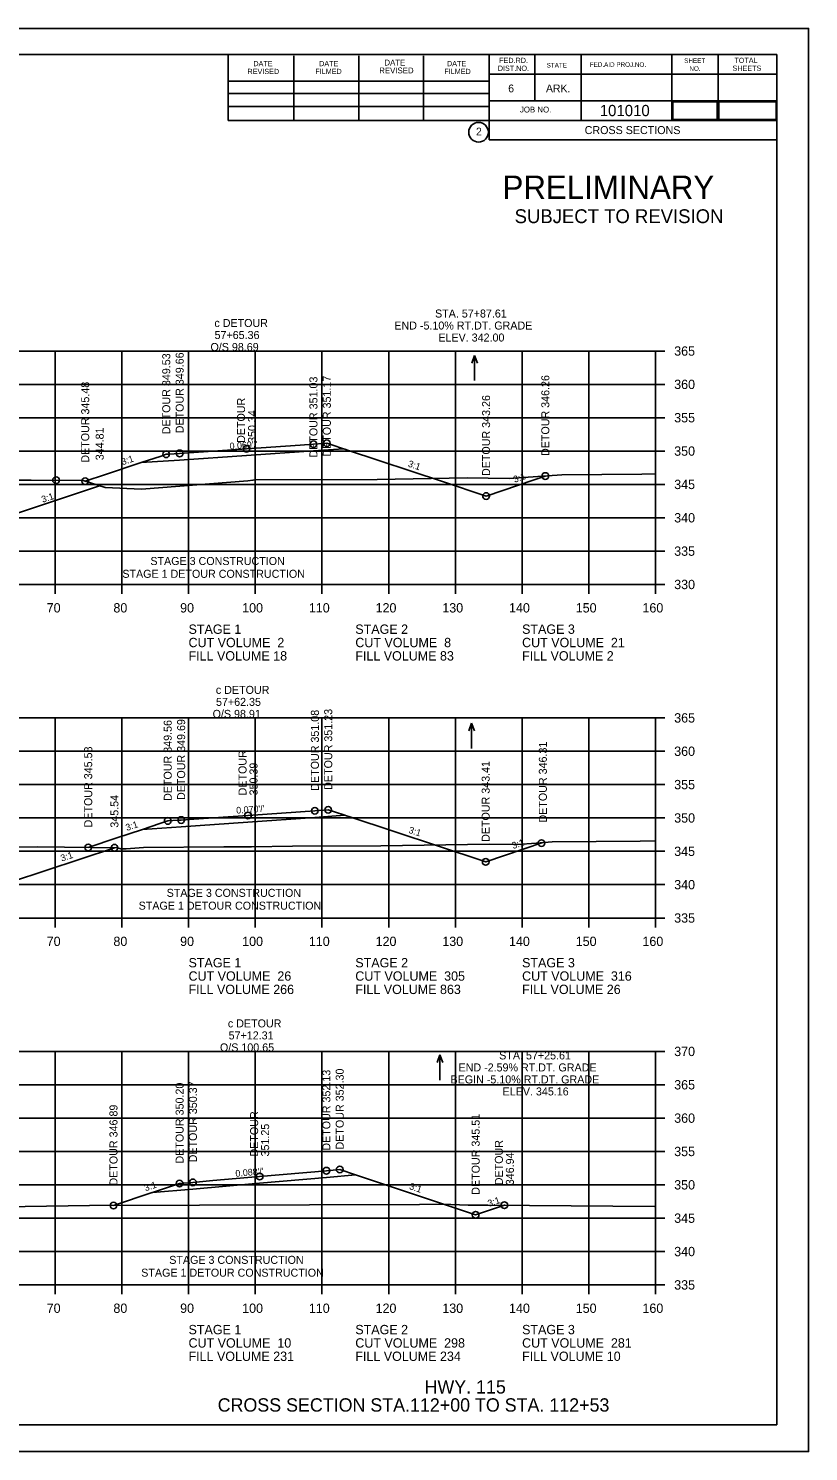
# Model space of a CAD drawing. Extents: x 1630712 to 1632516, y 782146 to 785403.
# Drawn here: x 1632399 to 1632515.9, y 784550 to 784763.3 of the extents above; entities that cross this region are included whole.
import ezdxf

# ---------------------------------------------------------------- set-up
doc = ezdxf.new("R2010")
doc.units = 0
for name, color, linetype in [('Default', 7, 'Continuous'), ('Notes', 7, 'Continuous'), ('Page Number', 7, 'Continuous'), ('R_Axis', 7, 'Continuous'), ('R_Axis Annot', 7, 'Continuous'), ('R_Border', 7, 'Continuous'), ('R_Border Notes', 7, 'Continuous'), ('R_Border Prem', 7, 'Continuous'), ('R_Detour Subgrade', 7, 'Continuous'), ('R_Detour Surface', 7, 'Continuous'), ('R_Draft', 7, 'Continuous'), ('R_Exist Surface', 7, 'Continuous'), ('R_Fin Surface', 7, 'Continuous'), ('R_Grid', 7, 'Continuous'), ('R_No Plot', 7, 'Continuous'), ('R_Water Annot', 7, 'Continuous'), ('R_Xsect Elev', 7, 'Continuous'), ('R_Xsect Elev Detour', 7, 'Continuous'), ('R_Xsect Slope', 7, 'Continuous'), ('Total_Pages', 7, 'Continuous')]:
    doc.layers.add(name, color=color, linetype=linetype)

msp = doc.modelspace()

# ---------------------------------------------------------------- linework, layer by layer
at = {"layer": 'Default'}
msp.add_line((1632396.41, 784635.37), (1632411.85, 784640.51), dxfattribs=at)
at = {"layer": 'Page Number'}
msp.add_lwpolyline([(1632495.54, 784749.7), (1632502.21, 784749.7), (1632502.21, 784752.34), (1632495.54, 784752.34)], close=True, dxfattribs=at)
at = {"layer": 'R_Axis'}
for p, q in [((1632492.96, 784679.97), (1632492.96, 784714.97)), ((1632494.36, 784714.97), (1632492.96, 784714.97)), ((1632494.36, 784709.97), (1632492.96, 784709.97)), ((1632494.36, 784704.97), (1632492.96, 784704.97)), ((1632494.36, 784699.97), (1632492.96, 784699.97)), ((1632494.36, 784694.97), (1632492.96, 784694.97)), ((1632494.36, 784689.97), (1632492.96, 784689.97)), ((1632494.36, 784684.97), (1632492.96, 784684.97)), ((1632212.96, 784679.97), (1632492.96, 784679.97)), ((1632402.96, 784678.57), (1632402.96, 784679.97)), ((1632412.96, 784678.57), (1632412.96, 784679.97)), ((1632422.96, 784678.57), (1632422.96, 784679.97)), ((1632432.96, 784678.57), (1632432.96, 784679.97)), ((1632442.96, 784678.57), (1632442.96, 784679.97)), ((1632452.96, 784678.57), (1632452.96, 784679.97)), ((1632462.96, 784678.57), (1632462.96, 784679.97)), ((1632472.96, 784678.57), (1632472.96, 784679.97)), ((1632482.96, 784678.57), (1632482.96, 784679.97)), ((1632492.96, 784678.57), (1632492.96, 784679.97)), ((1632494.36, 784679.97), (1632492.96, 784679.97)), ((1632492.96, 784629.97), (1632492.96, 784659.97)), ((1632494.36, 784659.97), (1632492.96, 784659.97)), ((1632494.36, 784654.97), (1632492.96, 784654.97)), ((1632494.36, 784649.97), (1632492.96, 784649.97)), ((1632494.36, 784644.97), (1632492.96, 784644.97)), ((1632494.36, 784639.97), (1632492.96, 784639.97)), ((1632494.36, 784634.97), (1632492.96, 784634.97)), ((1632212.96, 784629.97), (1632492.96, 784629.97)), ((1632402.96, 784628.57), (1632402.96, 784629.97)), ((1632412.96, 784628.57), (1632412.96, 784629.97)), ((1632422.96, 784628.57), (1632422.96, 784629.97)), ((1632432.96, 784628.57), (1632432.96, 784629.97)), ((1632442.96, 784628.57), (1632442.96, 784629.97)), ((1632452.96, 784628.57), (1632452.96, 784629.97)), ((1632462.96, 784628.57), (1632462.96, 784629.97)), ((1632472.96, 784628.57), (1632472.96, 784629.97)), ((1632482.96, 784628.57), (1632482.96, 784629.97)), ((1632492.96, 784628.57), (1632492.96, 784629.97)), ((1632494.36, 784629.97), (1632492.96, 784629.97)), ((1632492.96, 784574.97), (1632492.96, 784609.97)), ((1632494.36, 784609.97), (1632492.96, 784609.97)), ((1632494.36, 784604.97), (1632492.96, 784604.97)), ((1632494.36, 784599.97), (1632492.96, 784599.97)), ((1632494.36, 784594.97), (1632492.96, 784594.97)), ((1632494.36, 784589.97), (1632492.96, 784589.97)), ((1632494.36, 784584.97), (1632492.96, 784584.97)), ((1632494.36, 784579.97), (1632492.96, 784579.97)), ((1632212.96, 784574.97), (1632492.96, 784574.97)), ((1632402.96, 784573.57), (1632402.96, 784574.97)), ((1632412.96, 784573.57), (1632412.96, 784574.97)), ((1632422.96, 784573.57), (1632422.96, 784574.97)), ((1632432.96, 784573.57), (1632432.96, 784574.97)), ((1632442.96, 784573.57), (1632442.96, 784574.97)), ((1632452.96, 784573.57), (1632452.96, 784574.97)), ((1632462.96, 784573.57), (1632462.96, 784574.97)), ((1632472.96, 784573.57), (1632472.96, 784574.97)), ((1632482.96, 784573.57), (1632482.96, 784574.97)), ((1632492.96, 784573.57), (1632492.96, 784574.97)), ((1632494.36, 784574.97), (1632492.96, 784574.97))]:
    msp.add_line(p, q, dxfattribs=at)
at = {"layer": 'R_Border'}
for p, q in [((1632194.96, 784759.43), (1632511.14, 784759.43)), ((1632428.88, 784749.55), (1632428.88, 784759.43)), ((1632438.74, 784749.55), (1632438.74, 784759.23)), ((1632448.5, 784749.55), (1632448.5, 784759.23)), ((1632458.18, 784749.55), (1632458.18, 784759.23)), ((1632468.04, 784759.43), (1632468.04, 784746.63)), ((1632474.88, 784759.43), (1632474.88, 784752.49)), ((1632481.82, 784759.43), (1632481.82, 784749.55)), ((1632495.4, 784759.43), (1632495.4, 784749.55)), ((1632502.34, 784759.43), (1632502.34, 784749.55)), ((1632511.14, 784553.97), (1632511.14, 784759.43)), ((1632511.14, 784756.49), (1632468.04, 784756.49)), ((1632511.14, 784756.51), (1632511.14, 784756.51)), ((1632428.88, 784755.41), (1632468.04, 784755.41)), ((1632428.88, 784753.55), (1632468.04, 784753.55)), ((1632511.14, 784752.49), (1632468.04, 784752.49)), ((1632471, 784752.49), (1632511.14, 784752.49)), ((1632428.88, 784749.55), (1632428.88, 784751.61)), ((1632428.88, 784751.61), (1632468.04, 784751.61)), ((1632511.14, 784749.55), (1632428.88, 784749.55)), ((1632468.04, 784746.63), (1632511.14, 784746.63)), ((1632511.14, 784553.97), (1632194.96, 784553.97))]:
    msp.add_line(p, q, dxfattribs=at)
msp.add_circle((1632466.43, 784747.77), 1.47, dxfattribs=at)
at = {"layer": 'R_Detour Subgrade'}
for points in [[(1632415.85, 784698.24), (1632421.63, 784698.63), (1632431.66, 784699.31), (1632441.68, 784700), (1632446.19, 784700.31)], [(1632416.05, 784643.26), (1632421.85, 784643.66), (1632431.87, 784644.35), (1632441.9, 784645.05), (1632446.39, 784645.37)], [(1632417.54, 784588.8), (1632423.62, 784589.34), (1632433.62, 784590.22), (1632443.62, 784591.09), (1632447.99, 784591.48)]]:
    msp.add_lwpolyline(points, dxfattribs=at)
at = {"layer": 'R_Detour Surface'}
for points in [[(1632407.47, 784695.45), (1632410.52, 784696.46), (1632415.85, 784698.24), (1632418.84, 784699.23), (1632419.62, 784699.49), (1632420, 784699.52), (1632421.63, 784699.63), (1632431.64, 784700.31), (1632431.65, 784700.31), (1632431.66, 784700.31), (1632439.7, 784700.86), (1632441.68, 784701), (1632443.13, 784701.1), (1632443.69, 784701.14), (1632444.46, 784700.88), (1632446.19, 784700.31), (1632446.4, 784700.24), (1632446.79, 784700.11), (1632461.05, 784695.39), (1632467.56, 784693.23), (1632474.79, 784695.68), (1632476.44, 784696.23)], [(1632407.92, 784640.55), (1632412.23, 784641.99), (1632416.05, 784643.26), (1632418.66, 784644.13), (1632419.84, 784644.52), (1632421.35, 784644.63), (1632421.85, 784644.66), (1632423.74, 784644.79), (1632431.87, 784645.35), (1632431.88, 784645.36), (1632431.89, 784645.36), (1632441.9, 784646.05), (1632442.52, 784646.1), (1632443.9, 784646.19), (1632444.84, 784645.88), (1632446.39, 784645.37), (1632446.65, 784645.28), (1632446.99, 784645.17), (1632467.23, 784638.47), (1632467.5, 784638.38), (1632467.5, 784638.38), (1632476.07, 784641.28)], [(1632411.71, 784586.86), (1632417.53, 784588.8), (1632417.54, 784588.8), (1632417.54, 784588.81), (1632421.62, 784590.16), (1632421.62, 784590.16), (1632423.62, 784590.34), (1632423.62, 784590.34), (1632426.59, 784590.6), (1632433.62, 784591.22), (1632443.62, 784592.09), (1632445.62, 784592.27), (1632447.99, 784591.48), (1632447.99, 784591.48), (1632448.59, 784591.28), (1632448.59, 784591.28), (1632466, 784585.48), (1632466, 784585.48), (1632466, 784585.48), (1632470.3, 784586.91), (1632470.3, 784586.91), (1632470.3, 784586.91), (1632470.36, 784586.92), (1632470.36, 784586.92)]]:
    msp.add_lwpolyline(points, dxfattribs=at)
at = {"layer": 'R_Exist Surface'}
for points in [[(1632394.95, 784695.59), (1632399.38, 784695.62), (1632407.15, 784695.55), (1632410.48, 784694.51), (1632415.89, 784694.26), (1632431.85, 784695.51), (1632432.6, 784695.6), (1632432.85, 784695.65), (1632451.24, 784695.72), (1632464.73, 784695.94), (1632471.02, 784695.86), (1632475.3, 784696.16), (1632478.91, 784696.4), (1632490.89, 784696.53), (1632492.96, 784696.55)], [(1632393.57, 784640.58), (1632400.37, 784640.63), (1632412.31, 784640.51), (1632412.8, 784640.36), (1632413.59, 784640.32), (1632416.19, 784640.53), (1632428.24, 784640.65), (1632432.38, 784640.65), (1632438.53, 784640.74), (1632451.79, 784640.8), (1632468.02, 784641.06), (1632472.21, 784641.01), (1632475.06, 784641.21), (1632477.46, 784641.37), (1632490.67, 784641.51), (1632492.96, 784641.53)], [(1632385.52, 784586.5), (1632408.13, 784586.85), (1632457.56, 784587), (1632460.98, 784587.06), (1632464.86, 784586.91), (1632467.82, 784586.93), (1632492.79, 784586.74), (1632492.96, 784586.74)]]:
    msp.add_lwpolyline(points, dxfattribs=at)
at = {"layer": 'R_Fin Surface'}
for points in [[(1632396.41, 784690.37), (1632399.41, 784691.37), (1632409.63, 784694.78)], [(1632268.96, 784635.44), (1632269.96, 784635.11), (1632296.96, 784644.11), (1632310.78, 784646.18), (1632314.96, 784647.22), (1632320.96, 784647.46), (1632332.96, 784647.7), (1632344.96, 784647.46), (1632350.96, 784647.22), (1632355.15, 784646.18), (1632368.96, 784644.52), (1632396.41, 784635.37), (1632411.85, 784640.51)]]:
    msp.add_lwpolyline(points, dxfattribs=at)
at = {"layer": 'R_Grid'}
for p, q in [((1632212.96, 784714.97), (1632492.96, 784714.97)), ((1632402.96, 784679.97), (1632402.96, 784714.97)), ((1632412.96, 784679.97), (1632412.96, 784714.97)), ((1632422.96, 784679.97), (1632422.96, 784714.97)), ((1632432.96, 784679.97), (1632432.96, 784714.97)), ((1632442.96, 784679.97), (1632442.96, 784714.97)), ((1632452.96, 784679.97), (1632452.96, 784714.97)), ((1632462.96, 784679.97), (1632462.96, 784714.97)), ((1632472.96, 784679.97), (1632472.96, 784714.97)), ((1632482.96, 784679.97), (1632482.96, 784714.97)), ((1632492.96, 784679.97), (1632492.96, 784714.97)), ((1632212.96, 784709.97), (1632492.96, 784709.97)), ((1632212.96, 784704.97), (1632492.96, 784704.97)), ((1632212.96, 784699.97), (1632492.96, 784699.97)), ((1632212.96, 784694.97), (1632492.96, 784694.97)), ((1632212.96, 784689.97), (1632492.96, 784689.97)), ((1632212.96, 784684.97), (1632492.96, 784684.97)), ((1632212.96, 784679.97), (1632492.96, 784679.97)), ((1632212.96, 784659.97), (1632492.96, 784659.97)), ((1632402.96, 784629.97), (1632402.96, 784659.97)), ((1632412.96, 784629.97), (1632412.96, 784659.97)), ((1632422.96, 784629.97), (1632422.96, 784659.97)), ((1632432.96, 784629.97), (1632432.96, 784659.97)), ((1632442.96, 784629.97), (1632442.96, 784659.97)), ((1632452.96, 784629.97), (1632452.96, 784659.97)), ((1632462.96, 784629.97), (1632462.96, 784659.97)), ((1632472.96, 784629.97), (1632472.96, 784659.97)), ((1632482.96, 784629.97), (1632482.96, 784659.97)), ((1632492.96, 784629.97), (1632492.96, 784659.97)), ((1632212.96, 784654.97), (1632492.96, 784654.97)), ((1632212.96, 784649.97), (1632492.96, 784649.97)), ((1632212.96, 784644.97), (1632492.96, 784644.97)), ((1632212.96, 784639.97), (1632492.96, 784639.97)), ((1632212.96, 784634.97), (1632492.96, 784634.97)), ((1632212.96, 784629.97), (1632492.96, 784629.97)), ((1632212.96, 784609.97), (1632492.96, 784609.97)), ((1632402.96, 784574.97), (1632402.96, 784609.97)), ((1632412.96, 784574.97), (1632412.96, 784609.97)), ((1632422.96, 784574.97), (1632422.96, 784609.97)), ((1632432.96, 784574.97), (1632432.96, 784609.97)), ((1632442.96, 784574.97), (1632442.96, 784609.97)), ((1632452.96, 784574.97), (1632452.96, 784609.97)), ((1632462.96, 784574.97), (1632462.96, 784609.97)), ((1632472.96, 784574.97), (1632472.96, 784609.97)), ((1632482.96, 784574.97), (1632482.96, 784609.97)), ((1632492.96, 784574.97), (1632492.96, 784609.97)), ((1632212.96, 784604.97), (1632492.96, 784604.97)), ((1632212.96, 784599.97), (1632492.96, 784599.97)), ((1632212.96, 784594.97), (1632492.96, 784594.97)), ((1632212.96, 784589.97), (1632492.96, 784589.97)), ((1632212.96, 784584.97), (1632492.96, 784584.97)), ((1632212.96, 784579.97), (1632492.96, 784579.97)), ((1632212.96, 784574.97), (1632492.96, 784574.97))]:
    msp.add_line(p, q, dxfattribs=at)
at = {"layer": 'R_No Plot'}
for p, q in [((1632182.56, 784763.32), (1632515.9, 784763.32)), ((1632182.56, 784549.99), (1632515.9, 784549.99))]:
    msp.add_line(p, q, dxfattribs=at)
msp.add_lwpolyline([(1632182.56, 784763.32), (1632515.9, 784763.32), (1632515.9, 784549.99), (1632182.56, 784549.99)], close=True, dxfattribs=at)
for centre in [(1632431.66, 784700.31), (1632441.68, 784701), (1632443.69, 784701.14), (1632419.62, 784699.49), (1632421.63, 784699.63), (1632476.44, 784696.23), (1632403.1, 784695.59), (1632407.47, 784695.45), (1632467.56, 784693.23), (1632421.85, 784644.66), (1632431.87, 784645.35), (1632441.9, 784646.05), (1632443.9, 784646.19), (1632419.84, 784644.52), (1632407.92, 784640.55), (1632411.85, 784640.51), (1632475.85, 784641.2), (1632467.5, 784638.38), (1632433.62, 784591.22), (1632443.62, 784592.09), (1632445.62, 784592.27), (1632421.62, 784590.16), (1632423.62, 784590.34), (1632411.71, 784586.86), (1632466, 784585.48), (1632470.3, 784586.91)]:
    msp.add_circle(centre, 0.5, dxfattribs=at)
at = {"layer": 'R_Water Annot'}
for p, q in [((1632465.85, 784714.32), (1632465.43, 784713.16)), ((1632465.85, 784710.55), (1632465.85, 784714.32)), ((1632465.85, 784714.32), (1632466.27, 784713.16)), ((1632465.4, 784659.17), (1632464.98, 784658.01)), ((1632465.4, 784655.4), (1632465.4, 784659.17)), ((1632465.4, 784659.17), (1632465.82, 784658.01)), ((1632460.65, 784609.45), (1632460.23, 784608.3)), ((1632460.65, 784605.68), (1632460.65, 784609.45)), ((1632460.65, 784609.45), (1632461.07, 784608.3))]:
    msp.add_line(p, q, dxfattribs=at)
at = {"layer": 'Total_Pages'}
msp.add_lwpolyline([(1632502.44, 784749.7), (1632511.05, 784749.7), (1632511.05, 784752.34), (1632502.44, 784752.34)], close=True, dxfattribs=at)

# ---------------------------------------------------------------- texts
at = {"layer": 'Notes'}
for s, p in [('c DETOUR', (1632426.84, 784718.57)), ('STA. 57+87.61', (1632459.91, 784719.99)), ('57+65.36', (1632426.86, 784716.77)), ('END -5.10% RT.DT. GRADE ', (1632453.81, 784718.19)), ('ELEV. 342.00', (1632460.41, 784716.39)), ('O/S 98.69', (1632426.25, 784714.97)), ('STAGE 3 CONSTRUCTION', (1632417.24, 784682.89)), ('STAGE 1 DETOUR CONSTRUCTION', (1632413.04, 784680.97)), ('c DETOUR', (1632427.06, 784663.57)), ('57+62.35', (1632427.08, 784661.77)), ('O/S 98.91', (1632426.57, 784659.97)), ('STAGE 3 CONSTRUCTION', (1632419.68, 784633.14)), ('STAGE 1 DETOUR CONSTRUCTION', (1632415.48, 784631.22)), ('c DETOUR', (1632428.86, 784613.57)), ('O/S 100.65', (1632427.67, 784609.97)), ('57+12.31', (1632428.97, 784611.77)), ('STA. 57+25.61', (1632469.53, 784608.77)), ('END -2.59% RT.DT. GRADE', (1632463.43, 784606.97)), ('BEGIN -5.10% RT.DT. GRADE', (1632462.23, 784605.17)), ('ELEV. 345.16', (1632470.04, 784603.37)), ('STAGE 3 CONSTRUCTION', (1632420.07, 784578.12)), ('STAGE 1 DETOUR CONSTRUCTION', (1632415.87, 784576.2))]:
    msp.add_text(s, height=1.2, dxfattribs=at).set_placement(p)
at = {"layer": 'R_Axis Annot'}
for s, p in [('365', (1632495.76, 784714.27)), ('360', (1632495.76, 784709.27)), ('355', (1632495.76, 784704.27)), ('350', (1632495.76, 784699.27)), ('345', (1632495.76, 784694.27)), ('340', (1632495.76, 784689.27)), ('335', (1632495.76, 784684.27)), ('330', (1632495.76, 784679.27)), ('70', (1632401.7, 784675.77)), ('80', (1632411.7, 784675.77)), ('90', (1632421.7, 784675.77)), ('100', (1632431, 784675.77)), ('110', (1632441, 784675.77)), ('120', (1632451, 784675.77)), ('130', (1632461, 784675.77)), ('140', (1632471, 784675.77)), ('150', (1632481, 784675.77)), ('160', (1632491, 784675.77)), ('STAGE 1', (1632422.96, 784672.57)), ('STAGE 2', (1632447.96, 784672.57)), ('STAGE 3', (1632472.96, 784672.57)), ('CUT VOLUME  2', (1632422.96, 784670.57)), ('CUT VOLUME  8', (1632447.96, 784670.57)), ('CUT VOLUME  21', (1632472.96, 784670.57)), ('FILL VOLUME 18', (1632422.96, 784668.57)), ('FILL VOLUME 83', (1632447.96, 784668.57)), ('FILL VOLUME 2', (1632472.96, 784668.57)), ('365', (1632495.76, 784659.27)), ('360', (1632495.76, 784654.27)), ('355', (1632495.76, 784649.27)), ('350', (1632495.76, 784644.27)), ('345', (1632495.76, 784639.27)), ('340', (1632495.76, 784634.27)), ('335', (1632495.76, 784629.27)), ('70', (1632401.7, 784625.77)), ('80', (1632411.7, 784625.77)), ('90', (1632421.7, 784625.77)), ('100', (1632431, 784625.77)), ('110', (1632441, 784625.77)), ('120', (1632451, 784625.77)), ('130', (1632461, 784625.77)), ('140', (1632471, 784625.77)), ('150', (1632481, 784625.77)), ('160', (1632491, 784625.77)), ('STAGE 1', (1632422.96, 784622.57)), ('STAGE 2', (1632447.96, 784622.57)), ('STAGE 3', (1632472.96, 784622.57)), ('CUT VOLUME  26', (1632422.96, 784620.57)), ('CUT VOLUME  305', (1632447.96, 784620.57)), ('CUT VOLUME  316', (1632472.96, 784620.57)), ('FILL VOLUME 266', (1632422.96, 784618.57)), ('FILL VOLUME 863', (1632447.96, 784618.57)), ('FILL VOLUME 26', (1632472.96, 784618.57)), ('370', (1632495.76, 784609.27)), ('365', (1632495.76, 784604.27)), ('360', (1632495.76, 784599.27)), ('355', (1632495.76, 784594.27)), ('350', (1632495.76, 784589.27)), ('345', (1632495.76, 784584.27)), ('340', (1632495.76, 784579.27)), ('335', (1632495.76, 784574.27)), ('70', (1632401.7, 784570.77)), ('80', (1632411.7, 784570.77)), ('90', (1632421.7, 784570.77)), ('100', (1632431, 784570.77)), ('110', (1632441, 784570.77)), ('120', (1632451, 784570.77)), ('130', (1632461, 784570.77)), ('140', (1632471, 784570.77)), ('150', (1632481, 784570.77)), ('160', (1632491, 784570.77)), ('STAGE 1', (1632422.96, 784567.57)), ('STAGE 2', (1632447.96, 784567.57)), ('STAGE 3', (1632472.96, 784567.57)), ('CUT VOLUME  10', (1632422.96, 784565.57)), ('CUT VOLUME  298', (1632447.96, 784565.57)), ('CUT VOLUME  281', (1632472.96, 784565.57)), ('FILL VOLUME 231', (1632422.96, 784563.57)), ('FILL VOLUME 234', (1632447.96, 784563.57)), ('FILL VOLUME 10', (1632472.96, 784563.57))]:
    msp.add_text(s, height=1.4, dxfattribs=at).set_placement(p)
at = {"layer": 'R_Border'}
for s, height, p in [('DATE', 0.782, (1632432.68, 784757.67)), ('DATE', 0.782, (1632442.54, 784757.67)), ('DATE', 0.879, (1632452.32, 784757.77)), ('DATE', 0.782, (1632461.7, 784757.67)), ('FED.RD.', 0.782, (1632469.52, 784758.15)), ('STATE', 0.684, (1632476.64, 784757.47)), ('FED.AID PROJ.NO.', 0.684, (1632483.1, 784757.57)), ('SHEET', 0.684, (1632497.26, 784758.15)), ('TOTAL', 0.782, (1632504.78, 784758.15)), ('REVISED', 0.782, (1632431.8, 784756.49)), ('FILMED', 0.782, (1632441.96, 784756.49)), ('REVISED', 0.879, (1632451.54, 784756.59)), ('FILMED', 0.782, (1632461.3, 784756.49)), ('DIST.NO.', 0.782, (1632469.32, 784756.97)), ('NO.', 0.684, (1632498.04, 784756.97)), ('SHEETS', 0.782, (1632504.5, 784756.97)), ('6', 1.17, (1632470.88, 784753.75)), ('ARK.', 1.172, (1632476.54, 784753.75)), ('JOB NO.', 0.879, (1632472.64, 784750.73)), ('2', 1.17, (1632466.05, 784747.28))]:
    msp.add_text(s, height=height, rotation=360, dxfattribs=at).set_placement(p)
at = {"layer": 'R_Border Notes'}
for s, height, p in [('101010', 1.68, (1632484.6, 784750.18)), ('CROSS SECTIONS', 1.2, (1632482.34, 784747.49))]:
    msp.add_text(s, height=height, dxfattribs=at).set_placement(p)
at = {"layer": 'R_Border Prem'}
for s, height, p in [('PRELIMINARY', 3.5, (1632470.03, 784737.77)), ('SUBJECT TO REVISION', 2.0751, (1632471.84, 784734.14))]:
    msp.add_text(s, height=height, rotation=360, dxfattribs=at).set_placement(p)
at = {"layer": 'R_Draft'}
for s, p in [('HWY. 115', (1632458.34, 784558.68)), ('CROSS SECTION STA.112+00 TO STA. 112+53', (1632427.33, 784555.97))]:
    msp.add_text(s, height=2, dxfattribs=at).set_placement(p)
at = {"layer": 'R_Xsect Elev'}
for s, p in [('344.81', (1632410.24, 784698.59)), ('345.54', (1632412.45, 784643.51))]:
    msp.add_text(s, height=1.2, rotation=90, dxfattribs=at).set_placement(p)
at = {"layer": 'R_Xsect Elev Detour'}
for s, p in [('DETOUR 349.53', (1632420.22, 784702.49)), ('DETOUR 349.66', (1632422.23, 784702.63)), ('DETOUR 351.17', (1632444.29, 784699.14)), ('DETOUR 346.26', (1632477.04, 784699.23)), ('DETOUR 345.48', (1632408.07, 784698.23)), ('DETOUR 351.03', (1632442.28, 784699)), ('DETOUR', (1632431.43, 784701.19)), ('DETOUR 343.26', (1632468.16, 784696.23)), ('350.34', (1632433.08, 784701.19)), ('DETOUR 351.08', (1632442.5, 784649.05)), ('DETOUR 351.23', (1632444.5, 784649.19)), ('DETOUR 349.56', (1632420.44, 784647.52)), ('DETOUR 349.69', (1632422.45, 784647.66)), ('DETOUR 346.31', (1632476.67, 784644.28)), ('DETOUR 345.58', (1632408.52, 784643.55)), ('DETOUR', (1632431.65, 784648.35)), ('350.39', (1632433.3, 784648.35)), ('DETOUR 343.41', (1632468.1, 784641.38)), ('DETOUR 352.13', (1632444.22, 784595.09)), ('DETOUR 352.30', (1632446.22, 784595.27)), ('DETOUR 350.20', (1632422.22, 784593.16)), ('DETOUR 350.37', (1632424.22, 784593.34)), ('DETOUR 346.89', (1632412.31, 784589.86)), ('DETOUR', (1632433.39, 784594.22)), ('DETOUR 345.51', (1632466.6, 784588.48)), ('351.25', (1632435.04, 784594.22)), ('DETOUR', (1632470.08, 784589.91)), ('346.94', (1632471.73, 784589.91))]:
    msp.add_text(s, height=1.2, rotation=90, dxfattribs=at).set_placement(p)
at = {"layer": 'R_Xsect Slope'}
for s, rotation, p in [("0.069'/'", 3.932, (1632429.15, 784700.21)), ('3:1', 18.4222, (1632413.07, 784697.84)), ('3:1', 341.6778, (1632455.78, 784697.66)), ('3:1', 18.6741, (1632471.84, 784695.21)), ('3:1', 18.4349, (1632401.1, 784692.21)), ("0.070'/'", 3.9951, (1632430.14, 784645.61)), ('3:1', 18.4281, (1632413.72, 784643.01)), ('3:1', 341.6703, (1632455.86, 784642.76)), ('3:1', 18.671, (1632471.62, 784640.3)), ('3:1', 18.4349, (1632403.97, 784638.42)), ("0.088'/'", 5.0201, (1632430.03, 784591.17)), ('3:1', 18.4349, (1632416.51, 784588.99)), ('3:1', 341.565, (1632455.97, 784589.35)), ('3:1', 18.4349, (1632467.99, 784586.67))]:
    msp.add_text(s, height=1, rotation=rotation, dxfattribs=at).set_placement(p)

doc.saveas('drawing.dxf')
